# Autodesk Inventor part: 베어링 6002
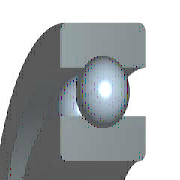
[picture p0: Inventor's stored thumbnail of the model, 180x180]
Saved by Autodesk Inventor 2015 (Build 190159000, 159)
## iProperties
Created: 2012-02
Part Number: 베어링 6002
Material: 강철, 연강
Description: 깊은 그루브 볼 베어링
Document SubType Name: Modeling
Standard: KS B 2023
Designer: mduedu
Standards Organization: KS
Language: ko-KR
Size Designation: 6002 - 15 x 32 x 9
Categories: <MemberInstance><Categories><Category DisplayName="샤프트 부품" InternalName="7f7aeb1f-a693-4053-b835-cee3144e0d98" Mnemonic="SHFT"><Category DisplayName="베어링" Inter
Density: 1 g/cm^3
Appearance: 노란색
IsCustomPart: 1
Author: mduedu
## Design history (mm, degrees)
sketch "스케치" dims "d0" = 4.42 (= -0.26 x WD + 0.26 x BD)
  geometry: L1 (2.29, 11.75)-(6.71, 11.75); L2 (4.5, 11.75)-(4.5, 9.54); L3 (4.5, 11.75)-(4.5, 13.96); L4 (2.858, 10.271)-(0, 10.271); L5 (0, 7.5)-(9, 7.5); L6 (2.858, 13.229)-(0, 13.229); L7 (0, 16)-(9, 16); L8 (9, 7.5)-(9, 10.271); L9 (6.142, 10.271)-(9, 10.271); L10 (6.142, 13.229)-(9, 13.229); L11 (9, 16)-(9, 13.229); L12 (-1.4, 0)-(8.4, 0) reference; L13 (0, -0.3)-(0, 5.3) reference
  constraints: 22 end point, 4 point on line, 2 collinear, 2 perpendicular, 2 symmetric about line, 1 midpoint, 1 parallel, 14 other
  dimensions: "d9" = 15 diameter of L5 L12 (= WD); "d11" = 32 diameter of L7 L12 (= BD); "d12" = 9 distance between parallel lines of L8 L13 (= KB); "d13" = 20.542 diameter of L9 L12 (= 0.326 x BD + 0.674 x WD)
revolve "본체" stored, may be unused: angle "d6" = 90 deg
revolve "볼" stored, may be unused: angle "d7" = 90 deg
pattern_circular "IDS_ARRAYBALL[SIMPL:T]" dims angle "d3" = 360 deg
body "Solid1"
fillet "모깎기1" dims "d1" = 0.3 (= KRS)
other parameters: "WD" = 15 [user parameter; used in 5 equation terms], "BD" = 32 [user parameter; used in 5 equation terms], "KB" = 9 [user parameter; used in 1 equation term], "KRS" = 0.3 [user parameter; used in 1 equation term], "d4" = 0, "d5" = 0, "d8" = 0, "d14" = 0, "d15" = 0, "BBA" = 0 [user parameter], "BC0" = 2850000 [user parameter], "BC" = 5590000 [user parameter], "BR" = 16 (= 0.5 x BD) [user parameter], "WR" = 7.5 (= 0.5 x WD) [user parameter]
